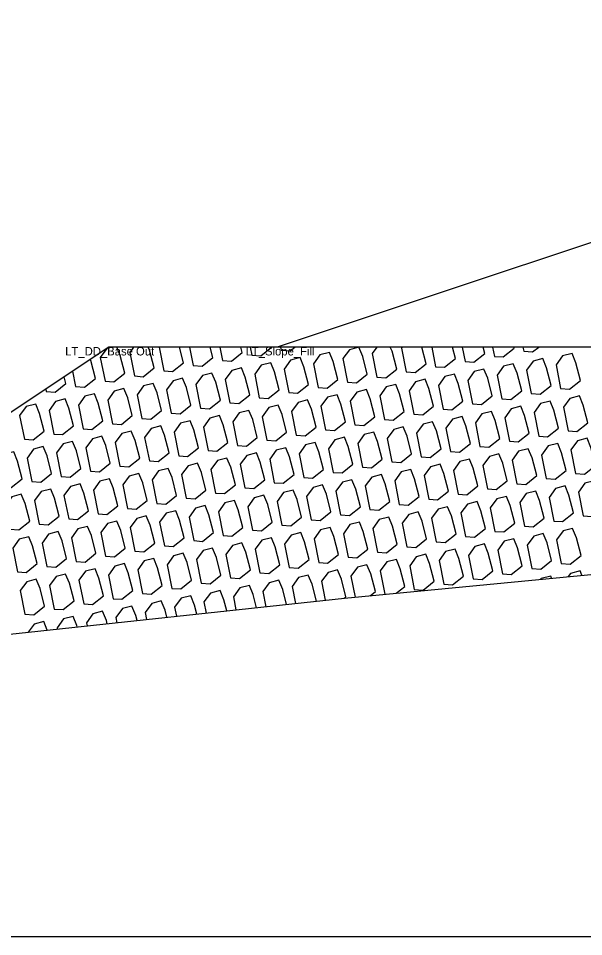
# Model space of a CAD drawing. Extents: x -26 to 203, y -10 to 20020.
# Drawn here: x 65.22 to 71.93, y 17000 to 17010.9 of the extents above; entities that cross this region are included whole.
import ezdxf

# ---------------------------------------------------------------- set-up
doc = ezdxf.new("R2010")
doc.units = 0
for name, color, linetype in [('Default', 7, 'Continuous'), ('Exist Cross Section Cell', 7, 'Continuous'), ('Exist XS Ground Line', 7, 'Continuous'), ('Old_Level_1', 7, 'Continuous'), ('Prop CMT Rip Rap Class II', 7, 'Continuous'), ('Prop CMT Slope Grass', 7, 'Continuous')]:
    doc.layers.add(name, color=color, linetype=linetype)

msp = doc.modelspace()

# ---------------------------------------------------------------- linework, layer by layer
at = {"layer": 'Exist Cross Section Cell'}
msp.add_line((0, 17000), (100, 17000), dxfattribs=at)
at = {"layer": 'Exist XS Ground Line'}
for p, q in [((69.089, 17004.017), (75.019, 17004.593)), ((63.819, 17003.451), (69.089, 17004.017))]:
    msp.add_line(p, q, dxfattribs=at)
at = {"layer": 'Old_Level_1'}
for p, q in [((67.25, 17007), (67.294, 17006.779)), ((67.611, 17007), (67.643, 17006.84)), ((67.972, 17007), (67.992, 17006.902)), ((68.333, 17007), (68.34, 17006.963)), ((70.126, 17007), (70.172, 17006.766)), ((70.486, 17007), (70.521, 17006.828)), ((70.847, 17007), (70.869, 17006.889)), ((71.208, 17007), (71.218, 17006.951)), ((65.864, 17006.714), (65.9, 17006.533)), ((65.545, 17006.501), (65.551, 17006.471))]:
    msp.add_line(p, q, dxfattribs=at)
for points in [[(66.345, 17007), (66.27, 17006.981), (66.193, 17006.874), (66.249, 17006.594)], [(66.249, 17006.594), (66.354, 17006.587), (66.483, 17006.69), (66.429, 17006.9), (66.388, 17007)], [(66.588, 17007), (66.542, 17006.936), (66.597, 17006.656)], [(66.597, 17006.656), (66.702, 17006.648), (66.832, 17006.751), (66.777, 17006.962), (66.762, 17007)], [(66.892, 17007), (66.89, 17006.997), (66.946, 17006.717)], [(66.946, 17006.717), (67.051, 17006.709), (67.181, 17006.813), (67.132, 17007)], [(67.294, 17006.779), (67.4, 17006.771), (67.529, 17006.874), (67.497, 17007)], [(67.643, 17006.84), (67.748, 17006.832), (67.878, 17006.936), (67.861, 17007)], [(67.992, 17006.902), (68.097, 17006.894), (68.226, 17006.997), (68.226, 17007)], [(68.34, 17006.963), (68.445, 17006.955), (68.501, 17007)], [(69.475, 17007), (69.419, 17006.923), (69.475, 17006.643)], [(69.475, 17006.643), (69.58, 17006.636), (69.71, 17006.739), (69.655, 17006.949), (69.634, 17007)], [(69.779, 17007), (69.768, 17006.985), (69.823, 17006.705)], [(69.823, 17006.705), (69.929, 17006.697), (70.058, 17006.8), (70.007, 17007)], [(70.172, 17006.766), (70.277, 17006.759), (70.407, 17006.862), (70.371, 17007)], [(70.521, 17006.828), (70.626, 17006.82), (70.755, 17006.923), (70.736, 17007)], [(70.869, 17006.889), (70.974, 17006.882), (71.104, 17006.985), (71.1, 17007)], [(71.218, 17006.951), (71.323, 17006.943), (71.395, 17007)], [(65.9, 17006.533), (66.005, 17006.525), (66.135, 17006.628), (66.08, 17006.839), (66.074, 17006.854)], [(68.429, 17006.459), (68.534, 17006.451), (68.664, 17006.554), (68.609, 17006.765), (68.564, 17006.875), (68.45, 17006.845), (68.373, 17006.739), (68.429, 17006.459)], [(65.551, 17006.471), (65.657, 17006.464), (65.786, 17006.567), (65.765, 17006.648)], [(68.518, 17005.955), (68.623, 17005.947), (68.753, 17006.05), (68.698, 17006.261), (68.653, 17006.371), (68.539, 17006.341), (68.462, 17006.235), (68.518, 17005.955)], [(68.607, 17005.451), (68.712, 17005.443), (68.842, 17005.546), (68.787, 17005.757), (68.742, 17005.867), (68.628, 17005.837), (68.551, 17005.731), (68.607, 17005.451)], [(68.696, 17004.947), (68.801, 17004.939), (68.93, 17005.042), (68.876, 17005.253), (68.831, 17005.363), (68.717, 17005.333), (68.64, 17005.227), (68.696, 17004.947)], [(68.785, 17004.443), (68.89, 17004.435), (69.019, 17004.538), (68.965, 17004.749), (68.92, 17004.858), (68.806, 17004.829), (68.729, 17004.723), (68.785, 17004.443)], [(69.705, 17004.077), (69.805, 17004.157), (69.751, 17004.368), (69.706, 17004.477), (69.592, 17004.448), (69.515, 17004.341), (69.57, 17004.064)], [(69.919, 17004.123), (70.024, 17004.115), (70.154, 17004.219), (70.1, 17004.429), (70.054, 17004.539), (69.941, 17004.509), (69.864, 17004.403), (69.919, 17004.123)], [(69.087, 17004.017), (69.108, 17004.034), (69.054, 17004.245), (69.009, 17004.354), (68.895, 17004.325), (68.818, 17004.219), (68.863, 17003.993)], [(69.396, 17004.047), (69.457, 17004.096), (69.402, 17004.306), (69.357, 17004.416), (69.243, 17004.386), (69.166, 17004.28), (69.216, 17004.03)], [(71.907, 17004.291), (71.886, 17004.342), (71.772, 17004.313), (71.746, 17004.275)], [(68.403, 17003.944), (68.357, 17004.122), (68.311, 17004.231), (68.198, 17004.202), (68.121, 17004.096), (68.156, 17003.917)], [(68.757, 17003.982), (68.705, 17004.183), (68.66, 17004.293), (68.546, 17004.264), (68.469, 17004.157), (68.509, 17003.955)], [(71.548, 17004.256), (71.538, 17004.281), (71.424, 17004.251), (71.418, 17004.244)], [(67.693, 17003.867), (67.659, 17003.999), (67.614, 17004.109), (67.5, 17004.079), (67.423, 17003.973), (67.45, 17003.841)], [(68.048, 17003.905), (68.008, 17004.06), (67.963, 17004.17), (67.849, 17004.141), (67.772, 17004.034), (67.803, 17003.879)], [(67.339, 17003.829), (67.311, 17003.937), (67.266, 17004.047), (67.152, 17004.018), (67.075, 17003.911), (67.096, 17003.803)], [(66.629, 17003.753), (66.614, 17003.814), (66.568, 17003.924), (66.455, 17003.895), (66.378, 17003.788), (66.39, 17003.727)], [(66.984, 17003.791), (66.962, 17003.876), (66.917, 17003.986), (66.803, 17003.956), (66.726, 17003.85), (66.743, 17003.765)], [(65.92, 17003.677), (65.916, 17003.692), (65.871, 17003.801), (65.757, 17003.772), (65.68, 17003.665), (65.683, 17003.651)], [(66.275, 17003.715), (66.265, 17003.753), (66.22, 17003.863), (66.106, 17003.833), (66.029, 17003.727), (66.036, 17003.689)], [(65.564, 17003.638), (65.523, 17003.74), (65.409, 17003.71), (65.339, 17003.614)]]:
    msp.add_lwpolyline(points, dxfattribs=at)
for points in [[(69.126, 17006.582), (69.231, 17006.574), (69.361, 17006.677), (69.307, 17006.888), (69.261, 17006.998), (69.148, 17006.968), (69.071, 17006.862)], [(68.778, 17006.52), (68.883, 17006.513), (69.012, 17006.616), (68.958, 17006.827), (68.913, 17006.936), (68.799, 17006.907), (68.722, 17006.8)], [(71.307, 17006.447), (71.412, 17006.439), (71.541, 17006.542), (71.487, 17006.753), (71.442, 17006.862), (71.328, 17006.833), (71.251, 17006.727)], [(71.655, 17006.508), (71.76, 17006.5), (71.89, 17006.604), (71.836, 17006.814), (71.79, 17006.924), (71.677, 17006.894), (71.6, 17006.788)], [(67.732, 17006.336), (67.837, 17006.328), (67.967, 17006.432), (67.912, 17006.642), (67.867, 17006.752), (67.753, 17006.722), (67.676, 17006.616)], [(68.08, 17006.397), (68.186, 17006.39), (68.315, 17006.493), (68.261, 17006.704), (68.216, 17006.813), (68.102, 17006.784), (68.025, 17006.677)], [(70.609, 17006.324), (70.715, 17006.316), (70.844, 17006.419), (70.79, 17006.63), (70.745, 17006.739), (70.631, 17006.71), (70.554, 17006.604)], [(70.958, 17006.385), (71.063, 17006.377), (71.193, 17006.481), (71.138, 17006.691), (71.093, 17006.801), (70.979, 17006.772), (70.902, 17006.665)], [(67.035, 17006.213), (67.14, 17006.205), (67.269, 17006.309), (67.215, 17006.519), (67.17, 17006.629), (67.056, 17006.599), (66.979, 17006.493)], [(67.383, 17006.275), (67.488, 17006.267), (67.618, 17006.37), (67.564, 17006.581), (67.518, 17006.69), (67.405, 17006.661), (67.328, 17006.554)], [(69.912, 17006.201), (70.018, 17006.193), (70.147, 17006.296), (70.093, 17006.507), (70.047, 17006.617), (69.934, 17006.587), (69.857, 17006.481)], [(70.261, 17006.262), (70.366, 17006.255), (70.496, 17006.358), (70.441, 17006.568), (70.396, 17006.678), (70.282, 17006.649), (70.205, 17006.542)], [(66.337, 17006.09), (66.443, 17006.082), (66.572, 17006.186), (66.518, 17006.396), (66.473, 17006.506), (66.359, 17006.477), (66.282, 17006.37)], [(66.686, 17006.152), (66.791, 17006.144), (66.921, 17006.247), (66.866, 17006.458), (66.821, 17006.567), (66.707, 17006.538), (66.63, 17006.432)], [(69.564, 17006.139), (69.669, 17006.132), (69.798, 17006.235), (69.744, 17006.445), (69.699, 17006.555), (69.585, 17006.526), (69.508, 17006.419)], [(65.989, 17006.029), (66.094, 17006.021), (66.224, 17006.124), (66.169, 17006.335), (66.124, 17006.444), (66.01, 17006.415), (65.933, 17006.309)], [(68.866, 17006.016), (68.972, 17006.009), (69.101, 17006.112), (69.047, 17006.322), (69.002, 17006.432), (68.888, 17006.403), (68.811, 17006.296)], [(69.215, 17006.078), (69.32, 17006.07), (69.45, 17006.173), (69.395, 17006.384), (69.35, 17006.494), (69.237, 17006.464), (69.159, 17006.358)], [(71.744, 17006.004), (71.849, 17005.996), (71.979, 17006.1), (71.924, 17006.31), (71.879, 17006.42), (71.766, 17006.39), (71.689, 17006.284)], [(65.292, 17005.906), (65.397, 17005.898), (65.526, 17006.001), (65.472, 17006.212), (65.427, 17006.322), (65.313, 17006.292), (65.236, 17006.186)], [(65.64, 17005.967), (65.745, 17005.96), (65.875, 17006.063), (65.821, 17006.273), (65.775, 17006.383), (65.662, 17006.354), (65.585, 17006.247)], [(68.169, 17005.893), (68.275, 17005.886), (68.404, 17005.989), (68.35, 17006.2), (68.304, 17006.309), (68.191, 17006.28), (68.114, 17006.173)], [(71.047, 17005.881), (71.152, 17005.873), (71.282, 17005.977), (71.227, 17006.187), (71.182, 17006.297), (71.068, 17006.267), (70.991, 17006.161)], [(71.396, 17005.943), (71.501, 17005.935), (71.63, 17006.038), (71.576, 17006.249), (71.531, 17006.358), (71.417, 17006.329), (71.34, 17006.222)], [(67.472, 17005.77), (67.577, 17005.763), (67.707, 17005.866), (67.652, 17006.077), (67.607, 17006.186), (67.494, 17006.157), (67.416, 17006.05)], [(67.821, 17005.832), (67.926, 17005.824), (68.055, 17005.927), (68.001, 17006.138), (67.956, 17006.248), (67.842, 17006.218), (67.765, 17006.112)], [(70.698, 17005.82), (70.804, 17005.812), (70.933, 17005.915), (70.879, 17006.126), (70.834, 17006.235), (70.72, 17006.206), (70.643, 17006.1)], [(67.123, 17005.709), (67.229, 17005.701), (67.358, 17005.805), (67.304, 17006.015), (67.259, 17006.125), (67.145, 17006.095), (67.068, 17005.989)], [(70.001, 17005.697), (70.106, 17005.689), (70.236, 17005.792), (70.181, 17006.003), (70.136, 17006.112), (70.023, 17006.083), (69.946, 17005.977)], [(70.35, 17005.758), (70.455, 17005.75), (70.585, 17005.854), (70.53, 17006.064), (70.485, 17006.174), (70.371, 17006.145), (70.294, 17006.038)], [(66.426, 17005.586), (66.532, 17005.578), (66.661, 17005.682), (66.607, 17005.892), (66.561, 17006.002), (66.448, 17005.972), (66.371, 17005.866)], [(66.775, 17005.648), (66.88, 17005.64), (67.01, 17005.743), (66.955, 17005.954), (66.91, 17006.063), (66.796, 17006.034), (66.719, 17005.927)], [(69.304, 17005.574), (69.409, 17005.566), (69.539, 17005.669), (69.484, 17005.88), (69.439, 17005.99), (69.325, 17005.96), (69.248, 17005.854)], [(69.653, 17005.635), (69.758, 17005.628), (69.887, 17005.731), (69.833, 17005.941), (69.788, 17006.051), (69.674, 17006.022), (69.597, 17005.915)], [(65.729, 17005.463), (65.834, 17005.455), (65.964, 17005.559), (65.909, 17005.769), (65.864, 17005.879), (65.751, 17005.85), (65.673, 17005.743)], [(66.078, 17005.525), (66.183, 17005.517), (66.312, 17005.62), (66.258, 17005.831), (66.213, 17005.94), (66.099, 17005.911), (66.022, 17005.805)], [(68.955, 17005.512), (69.061, 17005.505), (69.19, 17005.608), (69.136, 17005.818), (69.091, 17005.928), (68.977, 17005.899), (68.9, 17005.792)], [(71.484, 17005.438), (71.59, 17005.431), (71.719, 17005.534), (71.665, 17005.745), (71.62, 17005.854), (71.506, 17005.825), (71.429, 17005.718)], [(71.833, 17005.5), (71.938, 17005.492), (72.068, 17005.595), (72.013, 17005.806), (71.968, 17005.916), (71.854, 17005.886), (71.777, 17005.78)], [(65.032, 17005.34), (65.137, 17005.333), (65.267, 17005.436), (65.212, 17005.646), (65.167, 17005.756), (65.053, 17005.727), (64.976, 17005.62)], [(65.38, 17005.402), (65.486, 17005.394), (65.615, 17005.497), (65.561, 17005.708), (65.516, 17005.817), (65.402, 17005.788), (65.325, 17005.682)], [(67.91, 17005.328), (68.015, 17005.32), (68.144, 17005.423), (68.09, 17005.634), (68.045, 17005.744), (67.931, 17005.714), (67.854, 17005.608)], [(68.258, 17005.389), (68.363, 17005.382), (68.493, 17005.485), (68.439, 17005.695), (68.393, 17005.805), (68.28, 17005.776), (68.203, 17005.669)], [(71.136, 17005.377), (71.241, 17005.369), (71.371, 17005.473), (71.316, 17005.683), (71.271, 17005.793), (71.157, 17005.763), (71.08, 17005.657)], [(67.561, 17005.266), (67.666, 17005.259), (67.796, 17005.362), (67.741, 17005.573), (67.696, 17005.682), (67.582, 17005.653), (67.505, 17005.546)], [(70.439, 17005.254), (70.544, 17005.246), (70.673, 17005.35), (70.619, 17005.56), (70.574, 17005.67), (70.46, 17005.64), (70.383, 17005.534)], [(70.787, 17005.316), (70.892, 17005.308), (71.022, 17005.411), (70.968, 17005.622), (70.922, 17005.731), (70.809, 17005.702), (70.732, 17005.595)], [(66.864, 17005.143), (66.969, 17005.136), (67.099, 17005.239), (67.044, 17005.45), (66.999, 17005.559), (66.885, 17005.53), (66.808, 17005.423)], [(67.212, 17005.205), (67.318, 17005.197), (67.447, 17005.3), (67.393, 17005.511), (67.348, 17005.621), (67.234, 17005.591), (67.157, 17005.485)], [(69.741, 17005.131), (69.847, 17005.123), (69.976, 17005.227), (69.922, 17005.437), (69.877, 17005.547), (69.763, 17005.518), (69.686, 17005.411)], [(70.09, 17005.193), (70.195, 17005.185), (70.325, 17005.288), (70.27, 17005.499), (70.225, 17005.608), (70.111, 17005.579), (70.034, 17005.473)], [(66.167, 17005.02), (66.272, 17005.013), (66.401, 17005.116), (66.347, 17005.327), (66.302, 17005.436), (66.188, 17005.407), (66.111, 17005.3)], [(66.515, 17005.082), (66.62, 17005.074), (66.75, 17005.178), (66.696, 17005.388), (66.65, 17005.498), (66.537, 17005.468), (66.46, 17005.362)], [(69.044, 17005.008), (69.149, 17005.001), (69.279, 17005.104), (69.225, 17005.314), (69.179, 17005.424), (69.066, 17005.395), (68.989, 17005.288)], [(69.393, 17005.07), (69.498, 17005.062), (69.628, 17005.165), (69.573, 17005.376), (69.528, 17005.485), (69.414, 17005.456), (69.337, 17005.35)], [(65.469, 17004.898), (65.575, 17004.89), (65.704, 17004.993), (65.65, 17005.204), (65.605, 17005.313), (65.491, 17005.284), (65.414, 17005.178)], [(65.818, 17004.959), (65.923, 17004.951), (66.053, 17005.055), (65.998, 17005.265), (65.953, 17005.375), (65.839, 17005.345), (65.762, 17005.239)], [(71.573, 17004.934), (71.679, 17004.927), (71.808, 17005.03), (71.754, 17005.241), (71.708, 17005.35), (71.595, 17005.321), (71.518, 17005.214)], [(71.922, 17004.996), (72.027, 17004.988), (72.157, 17005.091), (72.102, 17005.302), (72.057, 17005.412), (71.943, 17005.382), (71.866, 17005.276)], [(65.121, 17004.836), (65.226, 17004.828), (65.356, 17004.932), (65.301, 17005.142), (65.256, 17005.252), (65.142, 17005.223), (65.065, 17005.116)], [(67.998, 17004.824), (68.104, 17004.816), (68.233, 17004.919), (68.179, 17005.13), (68.134, 17005.24), (68.02, 17005.21), (67.943, 17005.104)], [(68.347, 17004.885), (68.452, 17004.878), (68.582, 17004.981), (68.527, 17005.191), (68.482, 17005.301), (68.368, 17005.272), (68.291, 17005.165)], [(70.876, 17004.811), (70.981, 17004.804), (71.111, 17004.907), (71.056, 17005.118), (71.011, 17005.227), (70.898, 17005.198), (70.82, 17005.091)], [(71.225, 17004.873), (71.33, 17004.865), (71.459, 17004.968), (71.405, 17005.179), (71.36, 17005.289), (71.246, 17005.259), (71.169, 17005.153)], [(67.301, 17004.701), (67.407, 17004.693), (67.536, 17004.796), (67.482, 17005.007), (67.436, 17005.117), (67.323, 17005.087), (67.246, 17004.981)], [(67.65, 17004.762), (67.755, 17004.755), (67.885, 17004.858), (67.83, 17005.068), (67.785, 17005.178), (67.671, 17005.149), (67.594, 17005.042)], [(70.179, 17004.688), (70.284, 17004.681), (70.414, 17004.784), (70.359, 17004.995), (70.314, 17005.104), (70.2, 17005.075), (70.123, 17004.968)], [(70.527, 17004.75), (70.633, 17004.742), (70.762, 17004.846), (70.708, 17005.056), (70.663, 17005.166), (70.549, 17005.136), (70.472, 17005.03)], [(66.604, 17004.578), (66.709, 17004.57), (66.839, 17004.673), (66.784, 17004.884), (66.739, 17004.994), (66.626, 17004.964), (66.548, 17004.858)], [(66.953, 17004.639), (67.058, 17004.632), (67.187, 17004.735), (67.133, 17004.946), (67.088, 17005.055), (66.974, 17005.026), (66.897, 17004.919)], [(69.482, 17004.566), (69.587, 17004.558), (69.717, 17004.661), (69.662, 17004.872), (69.617, 17004.981), (69.503, 17004.952), (69.426, 17004.846)], [(69.83, 17004.627), (69.936, 17004.619), (70.065, 17004.723), (70.011, 17004.933), (69.966, 17005.043), (69.852, 17005.013), (69.775, 17004.907)], [(65.907, 17004.455), (66.012, 17004.447), (66.142, 17004.551), (66.087, 17004.761), (66.042, 17004.871), (65.928, 17004.841), (65.851, 17004.735)], [(66.255, 17004.516), (66.361, 17004.509), (66.49, 17004.612), (66.436, 17004.823), (66.391, 17004.932), (66.277, 17004.903), (66.2, 17004.796)], [(69.133, 17004.504), (69.238, 17004.496), (69.368, 17004.6), (69.313, 17004.81), (69.268, 17004.92), (69.155, 17004.891), (69.077, 17004.784)], [(65.558, 17004.393), (65.664, 17004.386), (65.793, 17004.489), (65.739, 17004.7), (65.693, 17004.809), (65.58, 17004.78), (65.503, 17004.673)], [(68.436, 17004.381), (68.541, 17004.374), (68.671, 17004.477), (68.616, 17004.687), (68.571, 17004.797), (68.457, 17004.768), (68.38, 17004.661)], [(71.314, 17004.369), (71.419, 17004.361), (71.548, 17004.464), (71.494, 17004.675), (71.449, 17004.785), (71.335, 17004.755), (71.258, 17004.649)], [(71.662, 17004.43), (71.767, 17004.423), (71.897, 17004.526), (71.843, 17004.736), (71.797, 17004.846), (71.684, 17004.817), (71.607, 17004.71)], [(65.21, 17004.332), (65.315, 17004.324), (65.444, 17004.428), (65.39, 17004.638), (65.345, 17004.748), (65.231, 17004.718), (65.154, 17004.612)], [(67.739, 17004.258), (67.844, 17004.251), (67.974, 17004.354), (67.919, 17004.564), (67.874, 17004.674), (67.76, 17004.645), (67.683, 17004.538)], [(68.087, 17004.32), (68.193, 17004.312), (68.322, 17004.415), (68.268, 17004.626), (68.223, 17004.736), (68.109, 17004.706), (68.032, 17004.6)], [(70.616, 17004.246), (70.722, 17004.238), (70.851, 17004.341), (70.797, 17004.552), (70.752, 17004.662), (70.638, 17004.632), (70.561, 17004.526)], [(70.965, 17004.307), (71.07, 17004.3), (71.2, 17004.403), (71.145, 17004.614), (71.1, 17004.723), (70.986, 17004.694), (70.909, 17004.587)], [(67.042, 17004.135), (67.147, 17004.128), (67.276, 17004.231), (67.222, 17004.441), (67.177, 17004.551), (67.063, 17004.522), (66.986, 17004.415)], [(67.39, 17004.197), (67.495, 17004.189), (67.625, 17004.292), (67.57, 17004.503), (67.525, 17004.613), (67.412, 17004.583), (67.335, 17004.477)], [(70.268, 17004.184), (70.373, 17004.177), (70.503, 17004.28), (70.448, 17004.491), (70.403, 17004.6), (70.289, 17004.571), (70.212, 17004.464)], [(66.693, 17004.074), (66.798, 17004.066), (66.928, 17004.169), (66.873, 17004.38), (66.828, 17004.49), (66.714, 17004.46), (66.637, 17004.354)], [(65.996, 17003.951), (66.101, 17003.943), (66.231, 17004.046), (66.176, 17004.257), (66.131, 17004.367), (66.017, 17004.337), (65.94, 17004.231)], [(66.344, 17004.012), (66.45, 17004.005), (66.579, 17004.108), (66.525, 17004.319), (66.48, 17004.428), (66.366, 17004.399), (66.289, 17004.292)], [(65.299, 17003.828), (65.404, 17003.82), (65.533, 17003.924), (65.479, 17004.134), (65.434, 17004.244), (65.32, 17004.214), (65.243, 17004.108)], [(65.647, 17003.889), (65.752, 17003.882), (65.882, 17003.985), (65.827, 17004.196), (65.782, 17004.305), (65.669, 17004.276), (65.592, 17004.169)]]:
    msp.add_lwpolyline(points, close=True, dxfattribs=at)
at = {"layer": 'Prop CMT Rip Rap Class II'}
msp.add_lwpolyline([(79.424, 17007), (66.293, 17007), (61.047, 17003.502)], dxfattribs=at)
at = {"layer": 'Prop CMT Slope Grass'}
msp.add_lwpolyline([(80, 17010.902), (68.293, 17007)], dxfattribs=at)

# ---------------------------------------------------------------- texts
at = {"layer": 'Default'}
for s, p in [('LT_DD_Base Out', (65.777, 17006.9)), ('LT_Slope_Fill', (67.917, 17006.9))]:
    msp.add_text(s, height=0.1, dxfattribs=at).set_placement(p)

doc.saveas('drawing.dxf')
